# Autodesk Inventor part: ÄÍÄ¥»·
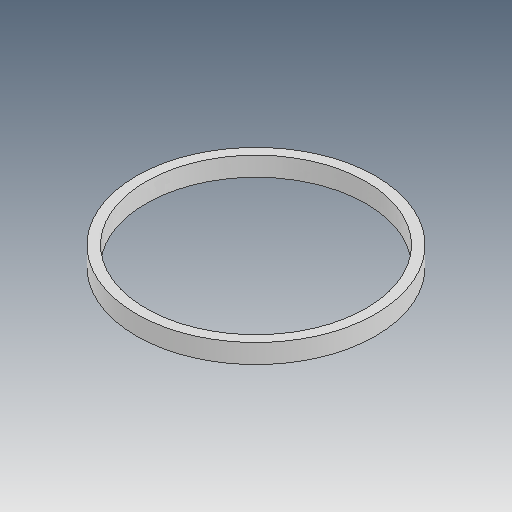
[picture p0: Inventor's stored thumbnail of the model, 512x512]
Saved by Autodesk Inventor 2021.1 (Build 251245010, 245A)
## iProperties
Created: 2014-12
Part Number: ÄÍÄ¥»·
Material: Ogólny
Document SubType Name: Modeling
Designer: user
Density: 1 g/cm^3
Appearance: Domyślna
Author: user
Revision Number: ÈÎºÎ
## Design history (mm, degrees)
feature "ÊäÈë1"
node "Bryła1"
